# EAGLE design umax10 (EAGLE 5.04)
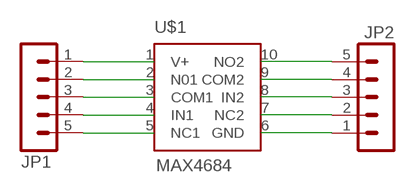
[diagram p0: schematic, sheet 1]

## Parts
JP1  MAR05-1  [MAR05-1]
JP2  MAR05-1  [MAR05-1]
U$1  MAX4684  [UMAX10]

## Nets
N$1: JP1.5 U$1.5(NC1)
N$2: JP1.4 U$1.4(IN1)
N$3: JP1.3 U$1.3(COM1)
N$4: JP1.2 U$1.2(N01)
N$5: JP1.1 U$1.1(V+)
N$6: JP2.1 U$1.6(GND)
N$7: JP2.2 U$1.7(NC2)
N$8: JP2.3 U$1.8(IN2)
N$9: JP2.4 U$1.9(COM2)
N$10: JP2.5 U$1.10(NO2)

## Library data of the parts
JP1 JP2 = con-lstb:MAR05-1: PIN HEADER
U$1 = trl:MAX4684

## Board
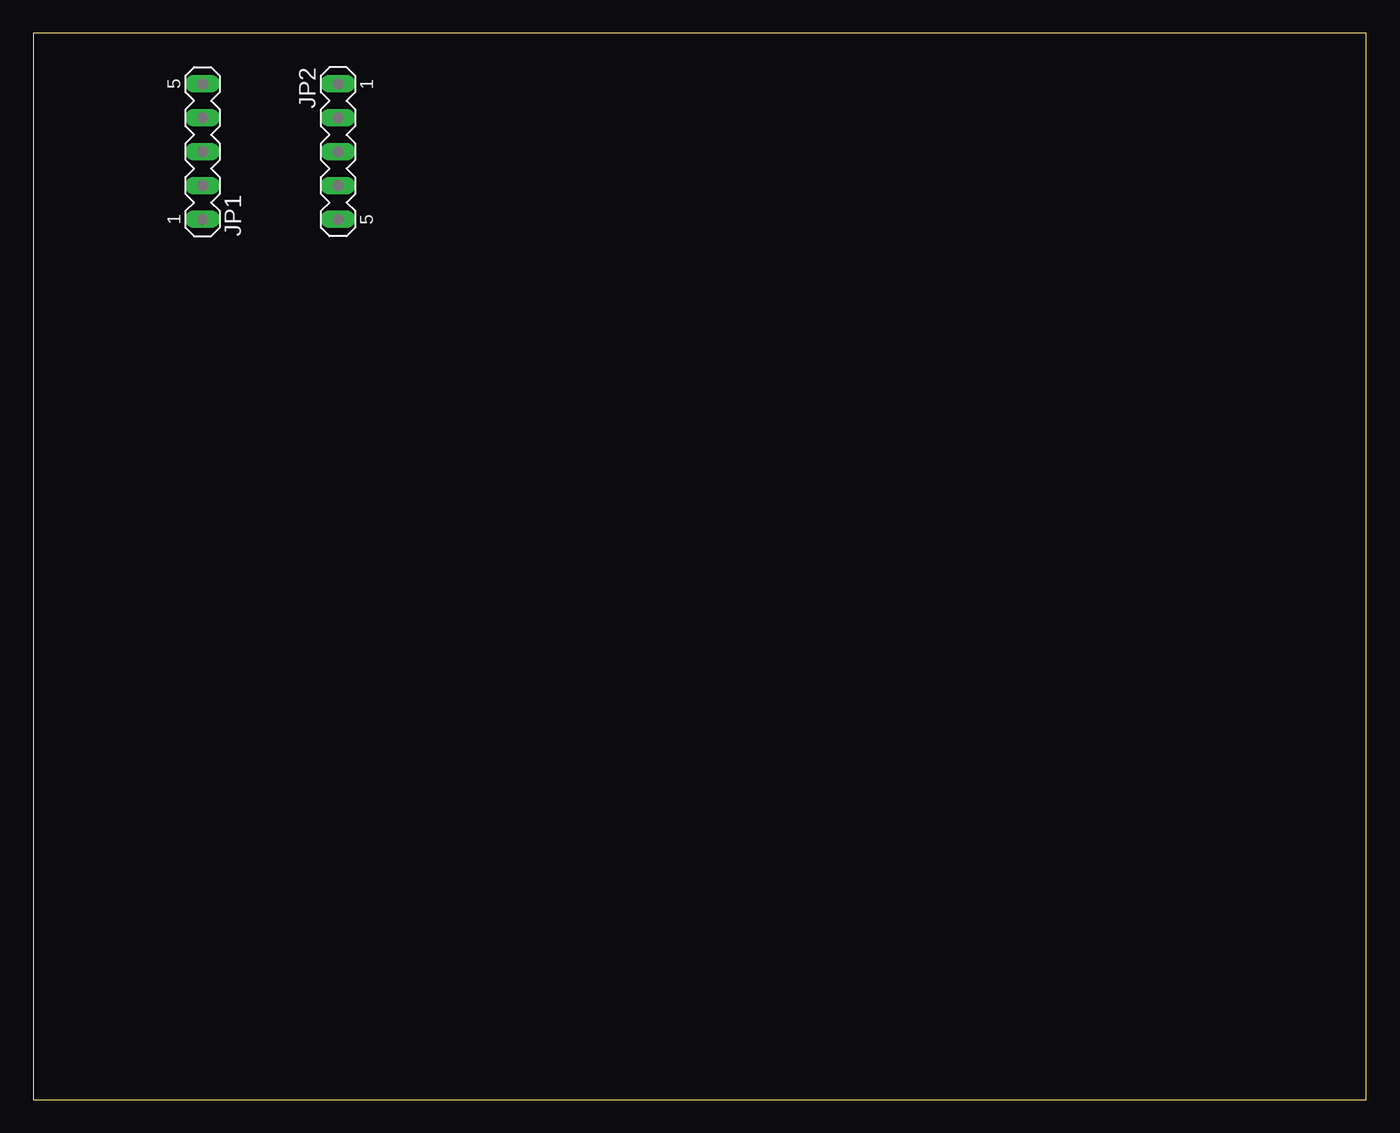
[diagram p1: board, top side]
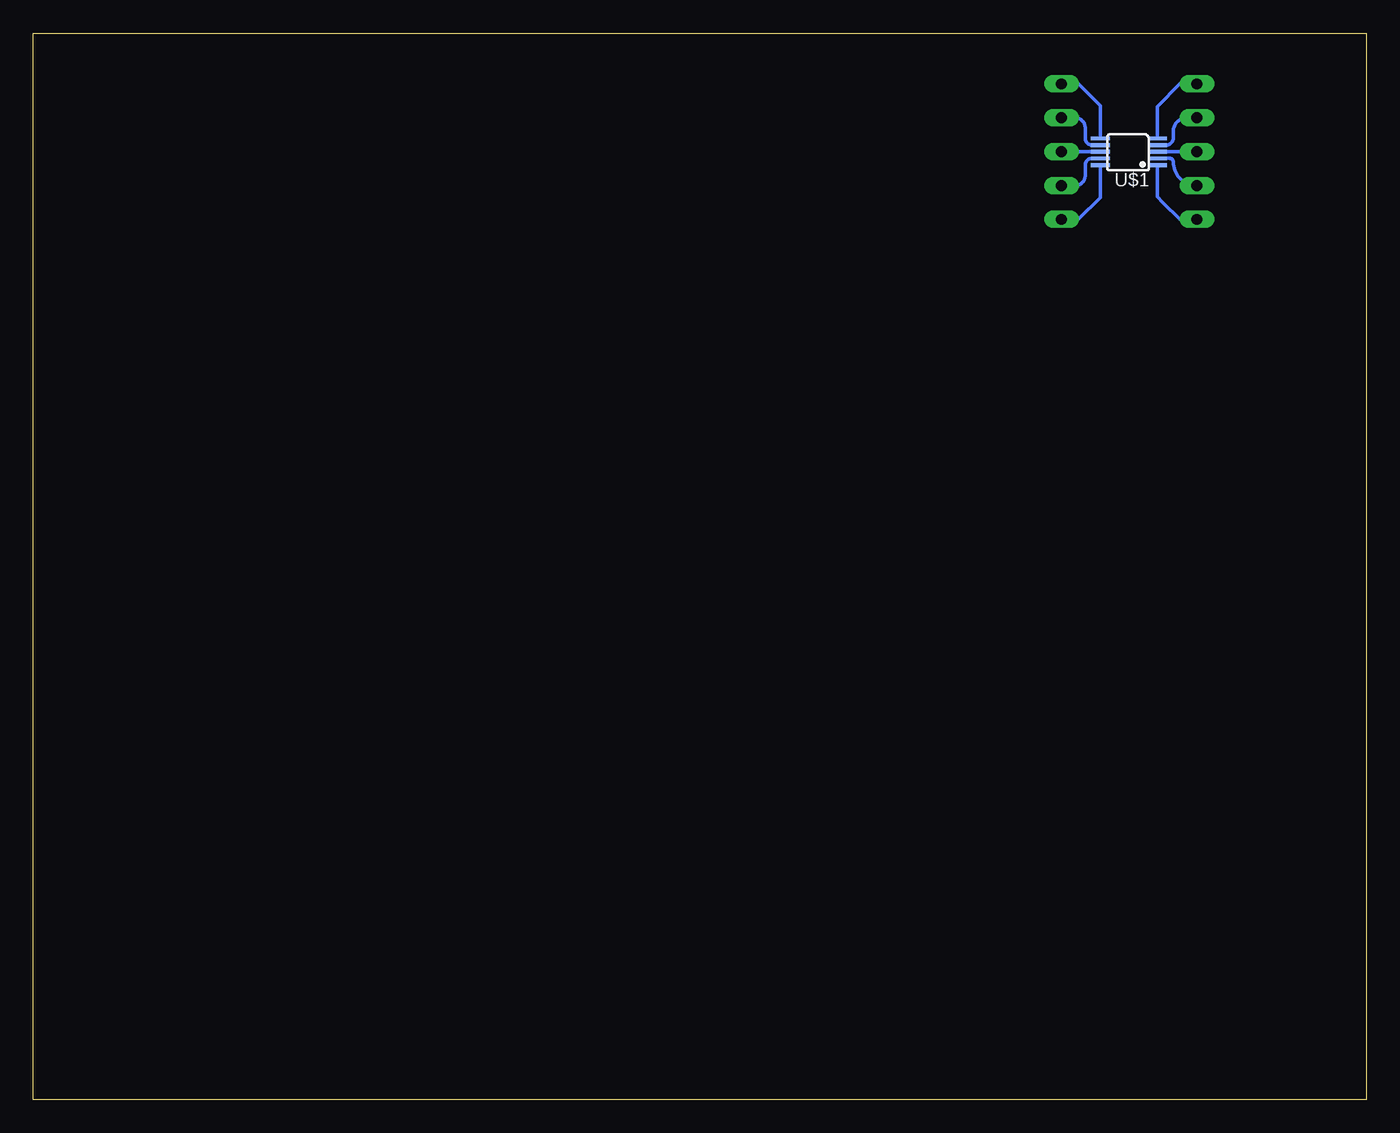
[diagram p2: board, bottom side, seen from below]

Size 100 x 80 mm. Coordinates in mm from the lower left corner, seen from the top.
Outline: 0,0 100,0 100,80 0,80 0,0
Copper layers (1*16): Top 0.035mm / dielectric 1.5mm / Bottom 0.035mm
Design rules "default": minimum track width 10mil, minimum drill 24mil, track to track 8mil, track to pad 8mil, pad to pad 8mil, via to via 8mil, smd to smd 8mil, copper to edge 40mil, drill to drill 8mil, minimum pad ring 10mil, minimum via ring 8mil, stop-mask expansion 4mil, vias tented up to drill 0mil, thermal gap 10mil

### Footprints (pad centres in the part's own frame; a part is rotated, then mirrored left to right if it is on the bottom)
MAR05-1 = drill 0.813 long: 1 -5.08,0; 2 -2.54,0; 3 0,0; 4 2.54,0; 5 5.08,0
UMAX10 = smd 1.4 x 0.28: 1 -2.37,1.26; 2 -2.37,0.76; 3 -2.37,0.26; 4 -2.37,-0.24; 5 -2.37,-0.74; 6 1.91,-0.74; 7 1.91,-0.24; 8 1.91,0.26; 9 1.91,0.76; 10 1.91,1.26

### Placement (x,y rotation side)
JP1  12.7,71.12 90 top
JP2  22.86,71.12 270 top
U$1  18.03,71.37 180 bottom

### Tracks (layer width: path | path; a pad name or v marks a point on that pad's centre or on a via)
N$1
  Bottom 0.254: U$1.5 15.66,74.51 13.97,76.2 JP1.5
N$2
  Bottom 0.254: U$1.4 15,71.61 arc-90 14.48,72.14 14.48,72.64 arc90 13.46,73.66 JP1.4
N$3
  Bottom 0.254: U$1.3 JP1.3
N$4
  Bottom 0.254: U$1.2 14.73,70.61 arc90 14.48,70.36 arc-90 JP1.2
N$5
  Bottom 0.254: U$1.1 15.66,67.73 15.24,67.31 13.97,66.04 JP1.1
N$6
  Bottom 0.254: U$1.6 19.94,74.55 21.59,76.2 JP2.1
N$7
  Bottom 0.254: U$1.7 20.56,71.61 arc90 21.08,72.14 21.08,72.9 arc-90 21.84,73.66 JP2.2
N$8
  Bottom 0.254: U$1.8 JP2.3
N$9
  Bottom 0.254: U$1.9 20.57,70.61 arc-90 21.08,70.1 21.08,69.34 arc90 21.84,68.58 JP2.4
N$10
  Bottom 0.254: U$1.10 19.94,67.69 21.59,66.04 JP2.5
